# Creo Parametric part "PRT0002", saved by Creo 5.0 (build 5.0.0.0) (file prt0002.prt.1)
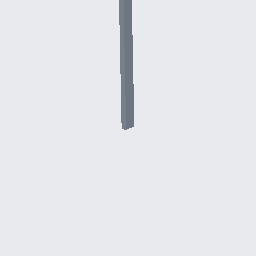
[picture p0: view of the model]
Units: Inch lbm Second (Pro/E Default); INCH, POUND, SECS

Created from: INLBS_PART_SOLID.PRT

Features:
  1. datum plane "RIGHT"
  2. datum plane "TOP"
  3. datum plane "FRONT"
  4. coordinate system
  5. sketch "Sketch 1"
  6. extrusion "Extrude 1"

Surfaces: 6 plane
